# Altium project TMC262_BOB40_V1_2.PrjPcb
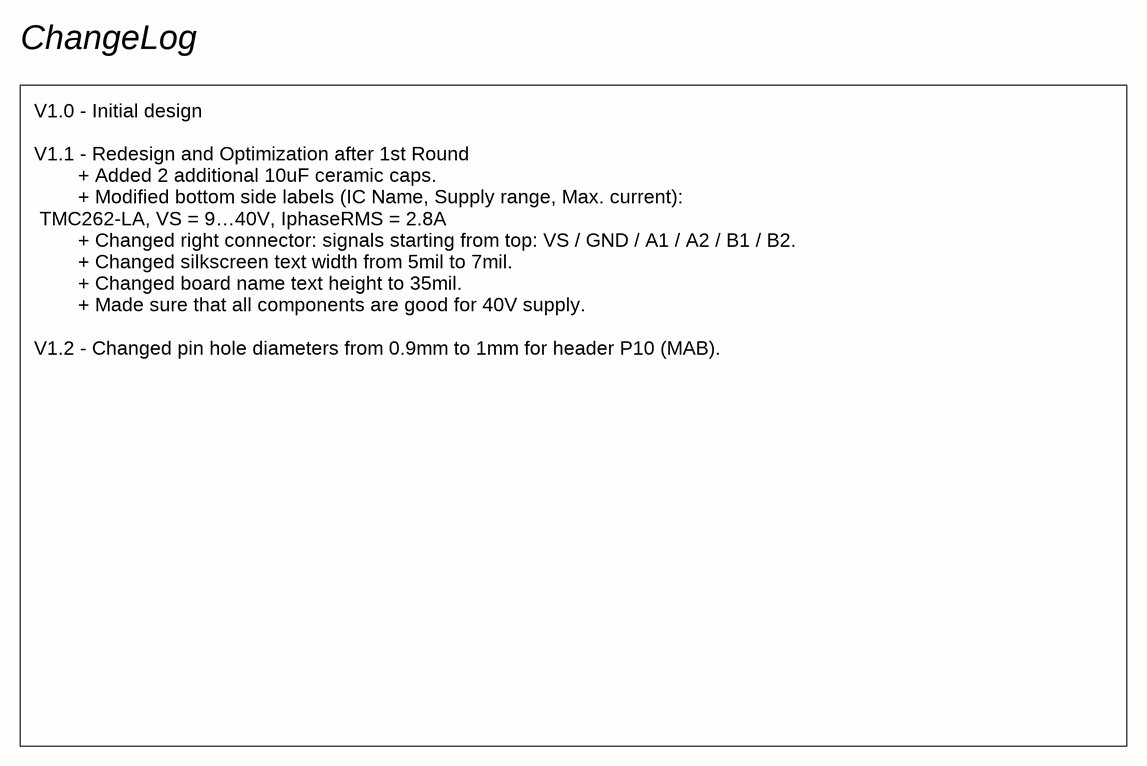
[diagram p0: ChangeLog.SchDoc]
BoardName: TMC262_BOB40; BoardVersion: 1.2; Chip: TMC262-LA; IRMS: 2.8A; VS: 9...40V
2 sheets, 33 parts. Net scope: global (net labels, ports and power ports of the same name join across sheets).
Board file: TMC262_BOB40_V1_2.PcbDoc
Sheets:
  ChangeLog.SchDoc
  TMC262_BOB40_V1_2.SchDoc

## Sheet ChangeLog.SchDoc
size A4

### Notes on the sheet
- ChangeLog
- V1.0 - Initial design
  V1.1 - Redesign and Optimization after 1st Round
  + Added 2 additional 10uF ceramic caps.
  + Modified bottom side labels (IC Name, Supply range, Max. current):
  TMC262-LA, VS = 9…40V, IphaseRMS = 2.8A
  + Changed right connector: signals starting from top: VS / GND / A1 / A2 / B1 / B2.
  + Changed silkscreen text width from 5mil to 7mil.
  + Changed board name text height to 35mil.
  + Made sure that all components are good for 40V supply.
  V1.2 - Changed pin hole diameters from 0.9mm to 1mm for header P10 (MAB).

## Sheet TMC262_BOB40_V1_2.SchDoc
size A4
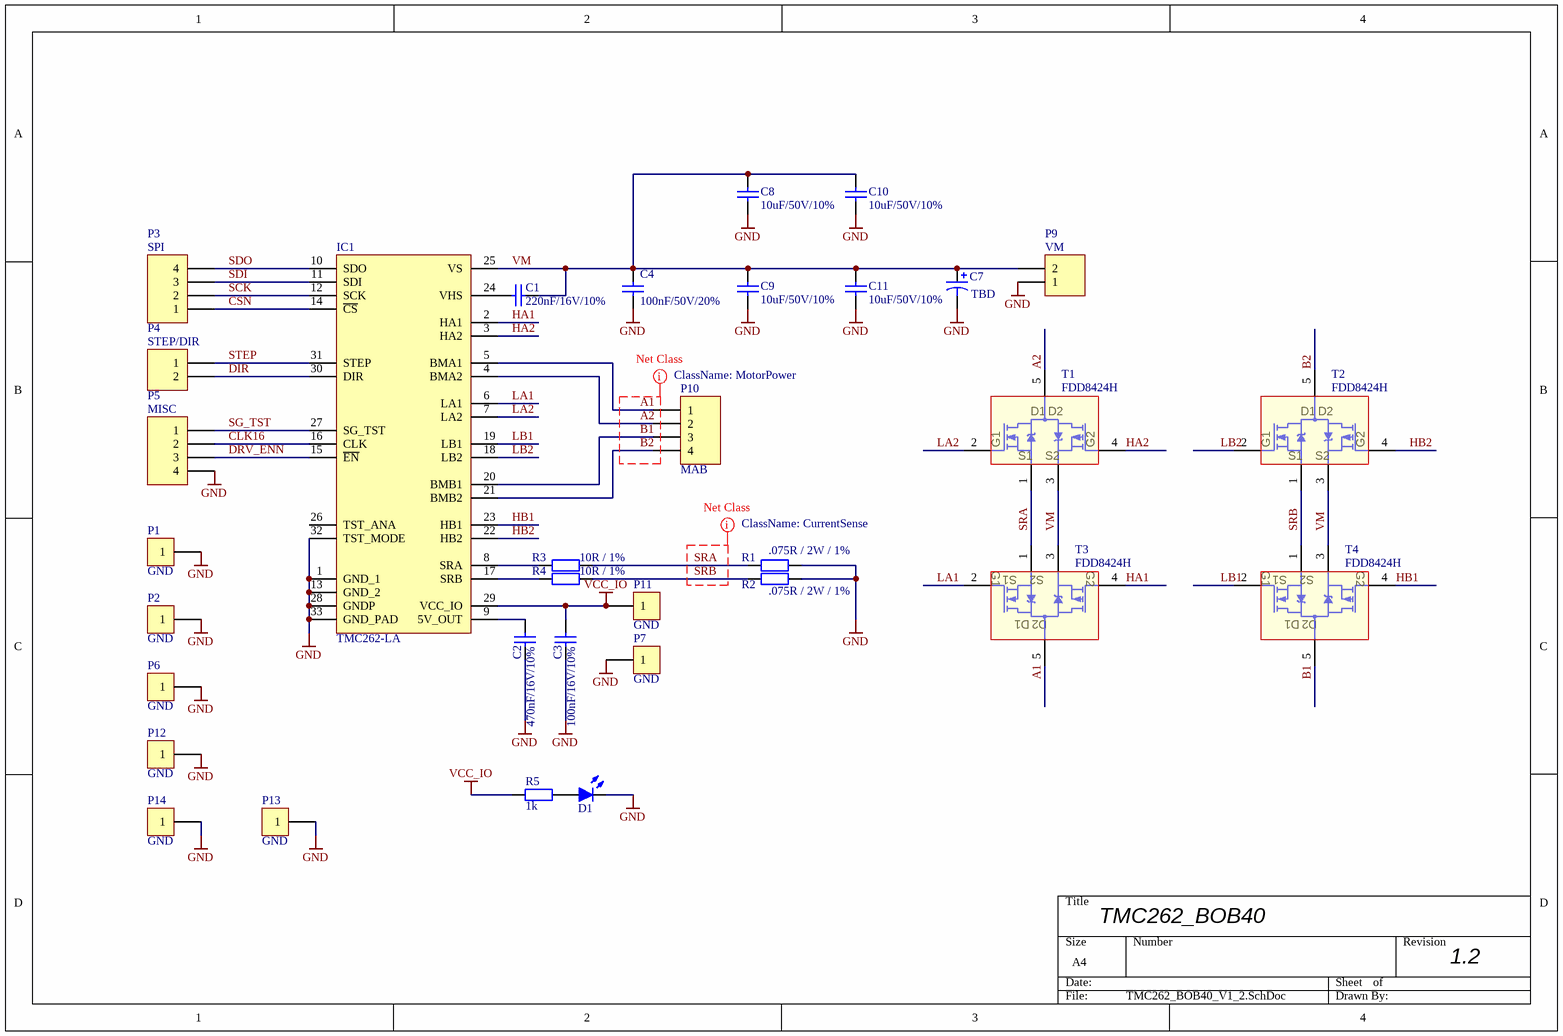
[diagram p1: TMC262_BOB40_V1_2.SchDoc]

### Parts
C1  220nF/16V/10%  [C0603]
C2  470nF/16V/10%  [C0603]
C3  100nF/16V/10%  [C0603]
C4  100nF/50V/20%  [C0603]
C7  value TBD  [EXT_POL_CAP]  (hidden comment: Cap Pol1)
C8  10uF/50V/10%  [C1206]
C9  10uF/50V/10%  [C1206]
C10  10uF/50V/10%  [C1206]
C11  10uF/50V/10%  [C1206]
D1  LED, Blue, SMD, 20mA, 2.8V, 465 nm  [LED_0603]  (value not drawn)
IC1  TMC262-LA  [TMC262_QFN32_0.5_5.0X5.0]
P1  GND  [TH_PIN]
P2  GND  [TH_PIN]
P3  SPI  [4_PIN_THT]
P4  STEP/DIR  [2_PIN_THT]
P5  MISC  [4_PIN_THT]
P6  GND  [TH_PIN]
P7  GND  [TH_PIN]
P9  VM  [2_PIN_THT]
P10  MAB  [4_PIN_THT_1mm_hole]
P11  GND  [TH_PIN]
P12  GND  [TH_PIN]
P13  GND  [TH_PIN]
P14  GND  [TH_PIN]
R1  .075R / 2W / 1%  [R2512]
R2  .075R / 2W / 1%  [R2512]
R3  10R / 1%  [R0603]
R4  10R / 1%  [R0603]
R5  1k  [R0603]
T1  FDD8424H  [SOT114P991X239-6N]
T2  FDD8424H  [SOT114P991X239-6N]
T3  FDD8424H  [SOT114P991X239-6N]
T4  FDD8424H  [SOT114P991X239-6N]

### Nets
GND: C2.2 C3.2 C4.1 C7.2 C8.1 C9.1 C10.1 C11.1 D1.2(K) IC1.1(GND_1) IC1.13(GND_2) IC1.28(GNDP) IC1.32(TST_MODE) IC1.33(GND_PAD) P1.1 P2.1 P5.4 P6.1 P7.1 P9.1 P12.1 P13.1 P14.1 R1.1 R2.1
VCC_IO: C3.1 IC1.29(VCC_IO) P11.1 R5.1
A1: IC1.5(BMA1) P10.1 T3.5(D1/D2)
A2: IC1.4(BMA2) P10.2 T1.5(D1/D2)
B1: IC1.20(BMB1) P10.3 T4.5(D1/D2)
B2: IC1.21(BMB2) P10.4 T2.5(D1/D2)
CLK16: IC1.16(CLK) P5.2
CSN: IC1.14(~{CS}) P3.1
DIR: IC1.30(DIR) P4.2
DRV_ENN: IC1.15(~{EN}) P5.3
HA1: IC1.2(HA1) T3.4(G2)
HA2: IC1.3(HA2) T1.4(G2)
HB1: IC1.23(HB1) T4.4(G2)
HB2: IC1.22(HB2) T2.4(G2)
LA1: IC1.6(LA1) T3.2(G1)
LA2: IC1.7(LA2) T1.2(G1)
LB1: IC1.19(LB1) T4.2(G1)
LB2: IC1.18(LB2) T2.2(G1)
SCK: IC1.12(SCK) P3.2
SDI: IC1.11(SDI) P3.3
SDO: IC1.10(SDO) P3.4
SG_TST: IC1.27(SG_TST) P5.1
SRA: R1.2 R3.1 T1.1(S1) T3.1(S1)
SRB: R2.2 R4.1 T2.1(S1) T4.1(S1)
STEP: IC1.31(STEP) P4.1
VM: C1.1 C4.2 C7.1 C8.2 C9.2 C10.2 C11.2 IC1.25(VS) P9.2 T1.3(S2) T2.3(S2) T3.3(S2) T4.3(S2)
NetC1_2: C1.2 IC1.24(VHS)
NetC2_1: C2.1 IC1.9(5V_OUT)
NetD1_1: D1.1(A) R5.2
NetIC1_8: IC1.8(SRA) R3.2
NetIC1_17: IC1.17(SRB) R4.2

Not connected (* = marked no-connect by the designer): IC1 26(TST_ANA)

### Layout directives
net class CurrentSense: SRA, SRB
net class MotorPower: A1, A2, B1, B2

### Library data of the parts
C1 = Capacitor: Ceramic capacitor; MPN: MC0603B224K160CT; Type: MLCC; VoltageRating: 16V; ComponentLinknDescription: Datasheet; MF: Multicomp; Capacitance: 220nF; Precision: 10%
C2 = Capacitor: Ceramic capacitor; MPN: MC0603X474K160CT; Type: MLCC; VoltageRating: 16V; ComponentLinknDescription: Datasheet; MF: Multicomp; Capacitance: 470nF; Precision: 10%
C3 = Capacitor: Ceramic capacitor; MPN: MC0603B104K160CT; Type: MLCC; VoltageRating: 16V; ComponentLinknDescription: Datasheet; MF: Multicomp; Capacitance: 100nF; Precision: 10%
C4 = Capacitor: Ceramic capacitor; MPN: MC0603F104M500CT; Type: MLCC; VoltageRating: 50V; ComponentLinknDescription: Datasheet; MF: Multicomp; Capacitance: 100nF; Precision: 20%
C7 = Cap Pol1: Polarized Capacitor (Radial); Fitted: Not fitted
C8-C11 = 10 µF, 50 V, ± 10%, X5R, 1206 [3216 Metric]: SMD Multilayer Ceramic Capacitor, 1206 [3216 Metric],10 µF, 50 V, ± 10%, X5R, GRM Series; MPN: GRM31CR61H106KA12L; Type: MLCC; VoltageRating: 50V; ComponentLinknDescription: Datasheet; MF: MURATA; Capacitance: 10uF
D1 = LED, Blue, SMD, 20mA, 2.8V, 465 nm: MPN: LTST-C191TBKT-5A; MF: Lite-On
IC1 = TMC262-LA: Energy saving high resolution microstepping two phase stepper driver with Step/Dir, SPI, up to 60V, QFN32(5x5); Manufacturer: TRINAMIC; Geometry.Height: 0,9mm; Ordercode - Distri#1: 1460-1044-ND; Ordercode - Distri#2: 1858307
P1 P2 P6 P7 P11-P14 = PIN: Note: n.b; Fitted: Not fitted
P3 P5 = Header 4: Header, 4-Pin; Fitted: Not fitted
P4 P9 = Header 2: Header, 2-Pin; Fitted: Not fitted
P10 = Wire-To-Board Connector, 2.5 mm, 4 Contacts, Header, EH Series, Through Hole, 1 Rows: MPN: B4B-EH-A; MF: JST (JAPAN SOLDERLESS TERMINALS); Fitted: Not fitted
R1 R2 = .075 OHM 2W 1% Current Sense Resistor: SMD Current Sense Resistor, 0.075 ohm, 2 W, 2512 [6432 Metric], ± 1%, TLR Series; MPN: TLR3A20WR075FTDG; ComponentLinknDescription: Datasheet; MF: TE CONNECTIVITY
R3 R4 = .05 OHM 2W 1% Current Sense Resistor: SMD Chip Resistor, Thick Film, 10 ohm, 50 V, 0603 [1608 Metric], 100 mW, ± 1%, MCWR Series; MPN: MCWR06X10R0FTL; PowerRating: 100mW; ComponentLinknDescription: Datasheet; MF: Multicomp
R5 = 1 kohm, 50 V, 0603 [1608 Metric], 63 mW, ± 1%, MC Series: MPN: MC0063W060311K; VoltageRating: 50V; Temp coefficient: *ppm; PowerRating: 63mW; MF: MULTICOMP
T1-T4 = FDD8424H: Dual MOSFET, N and P Channel, 9 A, 40 V, 0.019 ohm, 10 V, 1.7 V; MF: FAIRCHILD SEMICONDUCTOR

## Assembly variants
TMC262_BOB40_V1_1: not fitted C7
